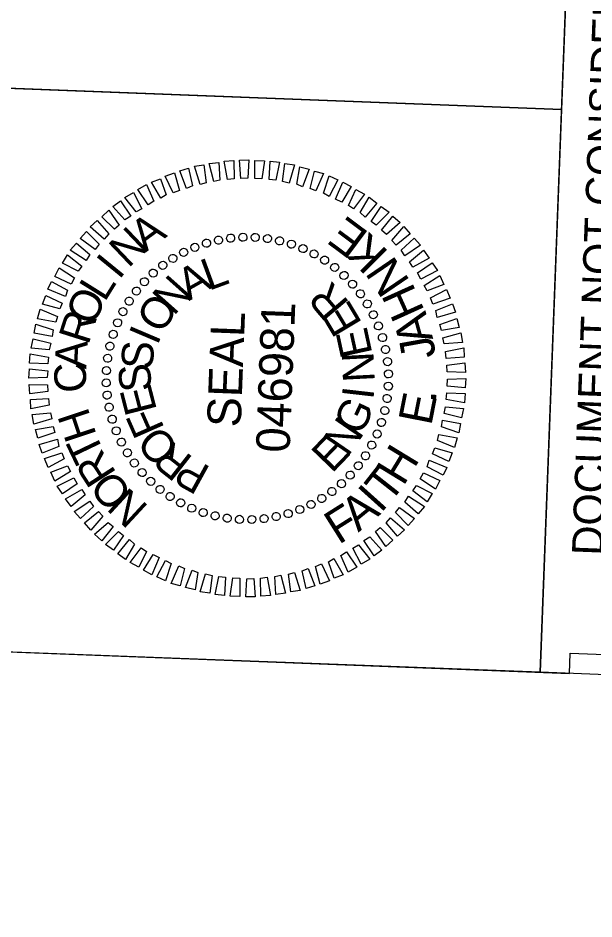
# Model space of a CAD drawing. Extents: x 2097521 to 2097987, y 686521 to 687299.
# Drawn here: x 2097571.8 to 2097612.8, y 687104.4 to 687168.4 of the extents above; entities that cross this region are included whole.
import ezdxf

# ---------------------------------------------------------------- set-up
doc = ezdxf.new("R2010")
doc.units = 0
for name, color, linetype in [('Sheet Layout Plan Border', 7, 'Continuous'), ('Sheet PE Seal Cell', 7, 'Continuous'), ('Sheet Profile CELL', 7, 'Continuous'), ('Sheet Sticker Exception Certification CELL', 7, 'Continuous')]:
    doc.layers.add(name, color=color, linetype=linetype)

msp = doc.modelspace()

# ---------------------------------------------------------------- linework, layer by layer
at = {"layer": 'Sheet Layout Plan Border'}
msp.add_lwpolyline([(2097534.777, 686624.292), (2097553.941, 687123.989), (2097611.015, 687121.8), (2097611.07, 687123.229), (2097798.297, 687116.048), (2097794.505, 687017.173), (2097779.163, 686617.133)], close=True, dxfattribs=at)
at = {"layer": 'Sheet PE Seal Cell'}
for p, q in [((2097586.055, 687152.587), (2097586.055, 687152.587)), ((2097586.941, 687152.714), (2097586.941, 687152.714)), ((2097587.805, 687152.801), (2097587.805, 687152.801)), ((2097588.685, 687152.787), (2097588.685, 687152.787)), ((2097589.562, 687152.693), (2097589.562, 687152.693)), ((2097590.416, 687152.52), (2097590.416, 687152.52)), ((2097584.395, 687152.091), (2097584.395, 687152.091)), ((2097585.207, 687152.38), (2097585.207, 687152.38)), ((2097591.248, 687152.308), (2097591.248, 687152.308)), ((2097592.077, 687151.996), (2097592.077, 687151.996)), ((2097582.823, 687151.29), (2097582.823, 687151.29)), ((2097583.6, 687151.721), (2097583.6, 687151.721)), ((2097592.863, 687151.606), (2097592.863, 687151.606)), ((2097593.627, 687151.176), (2097593.627, 687151.176)), ((2097582.104, 687150.818), (2097582.104, 687150.818)), ((2097594.327, 687150.649), (2097594.327, 687150.649)), ((2097581.422, 687150.243), (2097581.422, 687150.243)), ((2097595.006, 687150.083), (2097595.006, 687150.083)), ((2097580.799, 687149.647), (2097580.799, 687149.647)), ((2097595.602, 687149.459), (2097595.602, 687149.459)), ((2097580.232, 687148.968), (2097580.232, 687148.968)), ((2097596.177, 687148.777), (2097596.177, 687148.777)), ((2097579.705, 687148.268), (2097579.705, 687148.268)), ((2097596.649, 687148.058), (2097596.649, 687148.058)), ((2097579.275, 687147.504), (2097579.275, 687147.504)), ((2097597.08, 687147.281), (2097597.08, 687147.281)), ((2097578.885, 687146.718), (2097578.885, 687146.718)), ((2097597.45, 687146.486), (2097597.45, 687146.486)), ((2097578.573, 687145.889), (2097578.573, 687145.889)), ((2097597.739, 687145.675), (2097597.739, 687145.675)), ((2097578.361, 687145.057), (2097578.361, 687145.057)), ((2097597.947, 687144.826), (2097597.947, 687144.826)), ((2097578.188, 687144.203), (2097578.188, 687144.203)), ((2097598.073, 687143.941), (2097598.073, 687143.941)), ((2097578.094, 687143.326), (2097578.094, 687143.326)), ((2097598.16, 687143.077), (2097598.16, 687143.077)), ((2097578.081, 687142.446), (2097578.081, 687142.446)), ((2097588.12, 687142.761), (2097588.12, 687142.761)), ((2097598.146, 687142.196), (2097598.146, 687142.196)), ((2097578.168, 687141.582), (2097578.168, 687141.582)), ((2097598.052, 687141.319), (2097598.052, 687141.319)), ((2097578.294, 687140.696), (2097578.294, 687140.696)), ((2097597.879, 687140.465), (2097597.879, 687140.465)), ((2097578.501, 687139.848), (2097578.501, 687139.848)), ((2097597.667, 687139.633), (2097597.667, 687139.633)), ((2097578.791, 687139.036), (2097578.791, 687139.036)), ((2097597.355, 687138.804), (2097597.355, 687138.804)), ((2097579.16, 687138.241), (2097579.16, 687138.241)), ((2097596.965, 687138.019), (2097596.965, 687138.019)), ((2097579.591, 687137.464), (2097579.591, 687137.464)), ((2097596.535, 687137.255), (2097596.535, 687137.255)), ((2097580.064, 687136.745), (2097580.064, 687136.745)), ((2097596.008, 687136.554), (2097596.008, 687136.554)), ((2097580.638, 687136.063), (2097580.638, 687136.063)), ((2097595.442, 687135.875), (2097595.442, 687135.875)), ((2097581.235, 687135.44), (2097581.235, 687135.44)), ((2097594.818, 687135.279), (2097594.818, 687135.279)), ((2097581.913, 687134.873), (2097581.913, 687134.873)), ((2097594.136, 687134.705), (2097594.136, 687134.705)), ((2097582.614, 687134.346), (2097582.614, 687134.346)), ((2097583.378, 687133.916), (2097583.378, 687133.916)), ((2097593.417, 687134.232), (2097593.417, 687134.232)), ((2097584.163, 687133.526), (2097584.163, 687133.526)), ((2097584.992, 687133.214), (2097584.992, 687133.214)), ((2097591.845, 687133.432), (2097591.845, 687133.432)), ((2097592.64, 687133.801), (2097592.64, 687133.801)), ((2097585.824, 687133.002), (2097585.824, 687133.002)), ((2097586.678, 687132.829), (2097586.678, 687132.829)), ((2097587.556, 687132.735), (2097587.556, 687132.735)), ((2097588.436, 687132.722), (2097588.436, 687132.722)), ((2097589.3, 687132.809), (2097589.3, 687132.809)), ((2097590.185, 687132.935), (2097590.185, 687132.935)), ((2097591.034, 687133.142), (2097591.034, 687133.142))]:
    msp.add_line(p, q, dxfattribs=at)
for points in [[(2097586.7, 687156.886), (2097586.47, 687158.196), (2097587.152, 687158.23), (2097587.183, 687156.947)], [(2097587.664, 687156.969), (2097587.554, 687158.274), (2097588.235, 687158.288), (2097588.146, 687156.991)], [(2097588.664, 687156.951), (2097588.654, 687158.252), (2097589.334, 687158.226), (2097589.144, 687156.932)], [(2097589.663, 687156.892), (2097589.753, 687158.19), (2097590.411, 687158.125), (2097590.141, 687156.834)], [(2097583.794, 687156.257), (2097583.321, 687157.496), (2097583.949, 687157.692), (2097584.222, 687156.441)], [(2097584.766, 687156.54), (2097584.355, 687157.836), (2097585.019, 687157.931), (2097585.191, 687156.664)], [(2097585.734, 687156.743), (2097585.403, 687158.016), (2097586.087, 687158.11), (2097586.159, 687156.847)], [(2097590.618, 687156.756), (2097590.787, 687158.03), (2097591.464, 687157.924), (2097591.094, 687156.637)], [(2097591.631, 687156.557), (2097591.839, 687157.79), (2097592.513, 687157.624), (2097592.045, 687156.381)], [(2097581.966, 687155.566), (2097581.31, 687156.712), (2097581.939, 687156.948), (2097582.355, 687155.792)], [(2097582.841, 687155.933), (2097582.287, 687157.135), (2097582.936, 687157.371), (2097583.288, 687156.116)], [(2097592.581, 687156.26), (2097592.888, 687157.489), (2097593.542, 687157.324), (2097592.994, 687156.084)], [(2097593.529, 687155.924), (2097593.936, 687157.149), (2097594.545, 687156.865), (2097593.94, 687155.688)], [(2097581.067, 687155.08), (2097580.348, 687156.169), (2097580.962, 687156.526), (2097581.478, 687155.345)], [(2097594.393, 687155.49), (2097594.9, 687156.712), (2097595.508, 687156.388), (2097594.825, 687155.273)], [(2097580.228, 687154.592), (2097579.426, 687155.604), (2097580.02, 687155.961), (2097580.617, 687154.818)], [(2097595.297, 687155.055), (2097595.84, 687156.175), (2097596.448, 687155.852), (2097595.667, 687154.801)], [(2097596.138, 687154.543), (2097596.78, 687155.639), (2097597.324, 687155.218), (2097596.485, 687154.209)], [(2097579.425, 687154.023), (2097578.561, 687154.976), (2097579.117, 687155.375), (2097579.836, 687154.287)], [(2097596.914, 687153.912), (2097597.635, 687154.965), (2097598.2, 687154.563), (2097597.284, 687153.638)], [(2097578.679, 687153.351), (2097577.773, 687154.246), (2097578.271, 687154.707), (2097579.01, 687153.638)], [(2097577.952, 687152.658), (2097576.944, 687153.517), (2097577.442, 687153.979), (2097578.266, 687153.026)], [(2097597.65, 687153.284), (2097598.47, 687154.293), (2097598.972, 687153.833), (2097597.999, 687152.99)], [(2097577.303, 687151.922), (2097576.232, 687152.704), (2097576.692, 687153.207), (2097577.598, 687152.291)], [(2097598.383, 687152.555), (2097599.242, 687153.543), (2097599.682, 687153.026), (2097598.691, 687152.223)], [(2097599.057, 687151.869), (2097599.97, 687152.714), (2097600.432, 687152.216), (2097599.322, 687151.478)], [(2097576.672, 687151.126), (2097575.54, 687151.87), (2097575.98, 687152.373), (2097576.929, 687151.556)], [(2097599.646, 687151.045), (2097600.638, 687151.868), (2097601.037, 687151.312), (2097599.891, 687150.656)], [(2097576.103, 687150.367), (2097574.984, 687150.951), (2097575.347, 687151.537), (2097576.357, 687150.738)], [(2097575.608, 687149.466), (2097574.448, 687150.01), (2097574.751, 687150.619), (2097575.845, 687149.897)], [(2097600.217, 687150.263), (2097601.264, 687150.963), (2097601.624, 687150.429), (2097600.44, 687149.814)], [(2097600.682, 687149.365), (2097601.79, 687150.063), (2097602.086, 687149.431), (2097600.908, 687148.976)], [(2097575.194, 687148.581), (2097573.952, 687149.089), (2097574.214, 687149.639), (2097575.351, 687149.035)], [(2097574.799, 687147.695), (2097573.572, 687148.043), (2097573.795, 687148.654), (2097574.955, 687148.11)], [(2097601.129, 687148.487), (2097602.273, 687149.083), (2097602.529, 687148.453), (2097601.292, 687148.04)], [(2097601.515, 687147.591), (2097602.694, 687148.066), (2097602.911, 687147.458), (2097601.616, 687147.087)], [(2097574.503, 687146.746), (2097573.211, 687146.996), (2097573.397, 687147.669), (2097574.619, 687147.162)], [(2097601.797, 687146.6), (2097603.014, 687147.013), (2097603.17, 687146.387), (2097601.921, 687146.175)], [(2097574.244, 687145.735), (2097572.972, 687145.964), (2097573.097, 687146.62), (2097574.322, 687146.212)], [(2097602.02, 687145.631), (2097603.296, 687146.002), (2097603.409, 687145.317), (2097602.104, 687145.207)], [(2097574.047, 687144.782), (2097572.751, 687144.912), (2097572.896, 687145.567), (2097574.146, 687145.259)], [(2097602.203, 687144.663), (2097603.495, 687144.934), (2097603.529, 687144.272), (2097602.245, 687144.181)], [(2097573.949, 687143.785), (2097572.65, 687143.835), (2097572.695, 687144.494), (2097573.987, 687144.264)], [(2097573.892, 687142.826), (2097572.589, 687142.776), (2097572.635, 687143.435), (2097573.931, 687143.305)], [(2097602.287, 687143.699), (2097603.574, 687143.87), (2097603.628, 687143.187), (2097602.328, 687143.217)], [(2097573.954, 687141.823), (2097572.666, 687141.653), (2097572.612, 687142.335), (2097573.912, 687142.305)], [(2097602.348, 687142.696), (2097603.651, 687142.746), (2097603.606, 687142.087), (2097602.31, 687142.217)], [(2097602.291, 687141.737), (2097603.59, 687141.687), (2097603.545, 687141.029), (2097602.253, 687141.258)], [(2097574.037, 687140.859), (2097572.746, 687140.589), (2097572.711, 687141.251), (2097573.995, 687141.341)], [(2097574.22, 687139.892), (2097572.945, 687139.52), (2097572.831, 687140.205), (2097574.136, 687140.315)], [(2097602.193, 687140.74), (2097603.489, 687140.611), (2097603.344, 687139.956), (2097602.095, 687140.264)], [(2097601.996, 687139.787), (2097603.269, 687139.558), (2097603.143, 687138.903), (2097601.918, 687139.31)], [(2097574.443, 687138.922), (2097573.226, 687138.509), (2097573.07, 687139.135), (2097574.319, 687139.348)], [(2097574.725, 687137.931), (2097573.546, 687137.456), (2097573.329, 687138.065), (2097574.624, 687138.435)], [(2097601.737, 687138.776), (2097603.029, 687138.527), (2097602.843, 687137.853), (2097601.621, 687138.36)], [(2097601.441, 687137.827), (2097602.668, 687137.48), (2097602.445, 687136.868), (2097601.285, 687137.413)], [(2097575.111, 687137.035), (2097573.967, 687136.439), (2097573.711, 687137.069), (2097574.948, 687137.482)], [(2097575.558, 687136.158), (2097574.45, 687135.46), (2097574.154, 687136.091), (2097575.333, 687136.547)], [(2097601.047, 687136.941), (2097602.288, 687136.434), (2097602.027, 687135.883), (2097600.889, 687136.487)], [(2097600.632, 687136.057), (2097601.792, 687135.512), (2097601.489, 687134.903), (2097600.396, 687135.625)], [(2097576.024, 687135.259), (2097574.976, 687134.559), (2097574.616, 687135.093), (2097575.801, 687135.708)], [(2097600.138, 687135.155), (2097601.256, 687134.572), (2097600.893, 687133.985), (2097599.883, 687134.784)], [(2097576.594, 687134.477), (2097575.602, 687133.654), (2097575.203, 687134.21), (2097576.349, 687134.866)], [(2097577.183, 687133.654), (2097576.27, 687132.808), (2097575.809, 687133.306), (2097576.918, 687134.044)], [(2097599.568, 687134.396), (2097600.7, 687133.652), (2097600.261, 687133.149), (2097599.311, 687133.966)], [(2097577.857, 687132.967), (2097576.999, 687131.979), (2097576.558, 687132.497), (2097577.55, 687133.299)], [(2097598.937, 687133.6), (2097600.008, 687132.818), (2097599.548, 687132.315), (2097598.643, 687133.231)], [(2097598.288, 687132.864), (2097599.296, 687132.005), (2097598.798, 687131.544), (2097597.974, 687132.496)], [(2097578.59, 687132.239), (2097577.771, 687131.229), (2097577.268, 687131.689), (2097578.241, 687132.532)], [(2097597.561, 687132.172), (2097598.468, 687131.276), (2097597.97, 687130.815), (2097597.23, 687131.884)], [(2097579.326, 687131.61), (2097578.605, 687130.557), (2097578.04, 687130.959), (2097578.957, 687131.884)], [(2097580.103, 687130.98), (2097579.46, 687129.884), (2097578.916, 687130.305), (2097579.755, 687131.313)], [(2097596.815, 687131.5), (2097597.679, 687130.546), (2097597.123, 687130.147), (2097596.405, 687131.235)], [(2097580.944, 687130.467), (2097580.4, 687129.347), (2097579.792, 687129.671), (2097580.573, 687130.721)], [(2097596.013, 687130.93), (2097596.814, 687129.918), (2097596.22, 687129.561), (2097595.624, 687130.705)], [(2097581.848, 687130.032), (2097581.341, 687128.811), (2097580.733, 687129.134), (2097581.416, 687130.249)], [(2097595.173, 687130.442), (2097595.892, 687129.353), (2097595.278, 687128.997), (2097594.763, 687130.177)], [(2097582.712, 687129.599), (2097582.305, 687128.373), (2097581.695, 687128.657), (2097582.301, 687129.835)], [(2097583.66, 687129.262), (2097583.352, 687128.033), (2097582.698, 687128.198), (2097583.246, 687129.438)], [(2097593.399, 687129.589), (2097593.954, 687128.387), (2097593.304, 687128.152), (2097592.952, 687129.406)], [(2097594.274, 687129.956), (2097594.931, 687128.81), (2097594.301, 687128.574), (2097593.885, 687129.731)], [(2097584.609, 687128.966), (2097584.401, 687127.733), (2097583.727, 687127.899), (2097584.195, 687129.142)], [(2097585.622, 687128.767), (2097585.453, 687127.492), (2097584.777, 687127.598), (2097585.146, 687128.885)], [(2097590.506, 687128.779), (2097590.838, 687127.506), (2097590.153, 687127.412), (2097590.082, 687128.676)], [(2097591.475, 687128.982), (2097591.885, 687127.686), (2097591.221, 687127.591), (2097591.05, 687128.859)], [(2097592.446, 687129.265), (2097592.919, 687128.026), (2097592.291, 687127.83), (2097592.019, 687129.082)], [(2097586.577, 687128.63), (2097586.488, 687127.332), (2097585.83, 687127.398), (2097586.099, 687128.688)], [(2097587.576, 687128.572), (2097587.586, 687127.27), (2097586.907, 687127.296), (2097587.096, 687128.59)], [(2097588.576, 687128.553), (2097588.686, 687127.248), (2097588.005, 687127.234), (2097588.095, 687128.532)], [(2097589.54, 687128.636), (2097589.77, 687127.327), (2097589.088, 687127.293), (2097589.057, 687128.575)]]:
    msp.add_lwpolyline(points, close=True, dxfattribs=at)
for centre, major_axis in [((2097586.932, 687152.722), (-0.034, 0.286)), ((2097587.804, 687152.788), (-0.009, 0.288)), ((2097588.68, 687152.778), (0.016, 0.288)), ((2097584.394, 687152.075), (-0.107, 0.267)), ((2097585.22, 687152.365), (-0.083, 0.276)), ((2097586.068, 687152.581), (-0.059, 0.282)), ((2097589.55, 687152.691), (0.041, 0.285)), ((2097590.41, 687152.528), (0.066, 0.28)), ((2097591.253, 687152.291), (0.09, 0.274)), ((2097583.596, 687151.715), (-0.13, 0.257)), ((2097592.072, 687151.982), (0.113, 0.265)), ((2097592.86, 687151.603), (0.136, 0.254)), ((2097582.11, 687150.794), (-0.173, 0.231)), ((2097582.833, 687151.287), (-0.152, 0.245)), ((2097593.613, 687151.156), (0.158, 0.241)), ((2097581.433, 687150.239), (-0.192, 0.215)), ((2097594.324, 687150.645), (0.178, 0.226)), ((2097580.807, 687149.628), (-0.21, 0.197)), ((2097594.987, 687150.075), (0.197, 0.21)), ((2097580.236, 687148.964), (-0.226, 0.178)), ((2097595.598, 687149.448), (0.215, 0.192)), ((2097579.725, 687148.254), (-0.241, 0.158)), ((2097596.153, 687148.771), (0.231, 0.173)), ((2097596.646, 687148.048), (0.245, 0.152)), ((2097579.279, 687147.501), (-0.254, 0.136)), ((2097597.074, 687147.285), (0.257, 0.13)), ((2097578.899, 687146.713), (-0.265, 0.113)), ((2097597.434, 687146.487), (0.267, 0.107)), ((2097578.59, 687145.894), (-0.274, 0.09)), ((2097597.724, 687145.661), (0.276, 0.083)), ((2097578.353, 687145.051), (-0.28, 0.066)), ((2097597.94, 687144.813), (0.282, 0.059)), ((2097578.191, 687144.191), (-0.285, 0.041)), ((2097598.082, 687143.95), (0.286, 0.034)), ((2097578.104, 687143.32), (-0.288, 0.016)), ((2097598.147, 687143.077), (0.288, 0.009)), ((2097578.093, 687142.445), (-0.288, -0.009)), ((2097598.137, 687142.202), (0.288, -0.016)), ((2097578.159, 687141.573), (-0.286, -0.034)), ((2097598.05, 687141.331), (0.285, -0.041)), ((2097578.3, 687140.709), (-0.282, -0.059)), ((2097597.887, 687140.471), (0.28, -0.066)), ((2097578.517, 687139.861), (-0.276, -0.083)), ((2097597.65, 687139.628), (0.274, -0.09)), ((2097578.806, 687139.035), (-0.267, -0.107)), ((2097597.341, 687138.81), (0.265, -0.113)), ((2097579.166, 687138.237), (-0.257, -0.13)), ((2097596.962, 687138.021), (0.254, -0.136)), ((2097579.594, 687137.474), (-0.245, -0.152)), ((2097580.088, 687136.751), (-0.231, -0.173)), ((2097596.515, 687137.269), (0.241, -0.158)), ((2097580.642, 687136.074), (-0.215, -0.192)), ((2097596.004, 687136.558), (0.226, -0.178)), ((2097581.253, 687135.448), (-0.197, -0.21)), ((2097595.434, 687135.894), (0.21, -0.197)), ((2097581.917, 687134.877), (-0.178, -0.226)), ((2097594.807, 687135.283), (0.192, -0.215)), ((2097582.628, 687134.366), (-0.158, -0.241)), ((2097593.407, 687134.235), (0.152, -0.245)), ((2097594.13, 687134.729), (0.173, -0.231)), ((2097583.38, 687133.92), (-0.136, -0.254)), ((2097584.169, 687133.54), (-0.113, -0.265)), ((2097592.644, 687133.807), (0.13, -0.257)), ((2097584.987, 687133.231), (-0.09, -0.274)), ((2097585.83, 687132.994), (-0.066, -0.28)), ((2097590.172, 687132.941), (0.059, -0.282)), ((2097591.02, 687133.157), (0.083, -0.276)), ((2097591.846, 687133.447), (0.107, -0.267)), ((2097586.69, 687132.832), (-0.041, -0.285)), ((2097587.561, 687132.745), (-0.016, -0.288)), ((2097588.436, 687132.734), (0.009, -0.288)), ((2097589.309, 687132.8), (0.034, -0.286))]:
    msp.add_ellipse(centre, major_axis=major_axis, ratio=0.999708, dxfattribs=at)
at = {"layer": 'Sheet Profile CELL'}
msp.add_line((2097565.487, 687163.596), (2097610.434, 687161.872), dxfattribs=at)
for points in [[(2097565.487, 687163.596), (2097567.02, 687203.566), (2097611.987, 687201.842), (2097610.454, 687161.871)], [(2097563.954, 687123.605), (2097565.487, 687163.596), (2097610.454, 687161.871), (2097608.921, 687121.881)]]:
    msp.add_lwpolyline(points, close=True, dxfattribs=at)
at = {"layer": 'Sheet Sticker Exception Certification CELL'}
for p, q in [((2097608.921, 687121.881), (2097611.987, 687201.837)), ((2097618.314, 687121.52), (2097608.921, 687121.881))]:
    msp.add_line(p, q, dxfattribs=at)

# ---------------------------------------------------------------- texts
at = {"layer": 'Sheet PE Seal Cell'}
for s, height, rotation, p in [('A', 2.256, 36.42085, (2097580.877, 687151.685)), ('E', 2.399, 143.29672, (2097596.839, 687153.075)), ('N', 2.256, 43.62261, (2097579.652, 687150.551)), ('K', 2.399, 135.0128, (2097598.234, 687151.712)), ('I', 2.255, 50.82384, (2097579, 687149.716)), ('L', 2.256, 20.20455, (2097585.376, 687148.971)), ('N', 2.399, 124.28697, (2097599.723, 687149.673)), ('A', 2.256, 29.56397, (2097583.967, 687148.244)), ('N', 2.255, 48.28031, (2097582.884, 687147.145)), ('L', 2.255, 58.02457, (2097577.979, 687148.134)), ('R', 2.256, 130.28511, (2097595.431, 687148.125)), ('H', 2.399, 114.30299, (2097600.745, 687147.557)), ('O', 2.255, 65.22486, (2097577.172, 687146.403)), ('O', 2.255, 57.63718, (2097582.034, 687145.837)), ('046981', 2.3993, 87.8037, (2097591.122, 687137.454)), ('E', 2.255, 120.92779, (2097596.316, 687146.67)), ('R', 2.255, 72.4248, (2097576.821, 687145.076)), ('SEAL', 2.3993, 87.8037, (2097587.646, 687139.257)), ('A', 2.399, 105.46268, (2097601.333, 687145.56)), ('I', 2.255, 66.9933, (2097581.723, 687145.048)), ('E', 2.255, 102.21546, (2097597.014, 687144.522)), ('A', 2.255, 86.82402, (2097576.676, 687143.4)), ('J', 2.399, 100.20486, (2097601.533, 687144.337)), ('S', 2.255, 85.7041, (2097581.377, 687143.34)), ('N', 2.255, 92.86009, (2097597.178, 687142.534)), ('C', 2.255, 94.02357, (2097576.736, 687141.817)), ('S', 2.255, 95.05931, (2097581.342, 687141.9)), ('E', 2.255, 104.41477, (2097581.709, 687140.505)), ('I', 2.255, 83.5049, (2097597.067, 687141.197)), ('E', 2.399, 78.86139, (2097601.187, 687139.347)), ('.', 2.399, 85.97073, (2097601.509, 687140.991)), ('G', 2.255, 64.79394, (2097596.207, 687138.608)), ('H', 2.255, 108.42318, (2097577.419, 687138.748)), ('F', 2.255, 113.77073, (2097582.26, 687139.203)), ('N', 2.255, 55.43766, (2097595.249, 687137.124)), ('O', 2.256, 132.48494, (2097583.388, 687137.839)), ('T', 2.255, 115.62347, (2097578.028, 687137.424)), ('R', 2.256, 141.84335, (2097584.341, 687137.102)), ('E', 2.255, 46.08059, (2097594.124, 687135.966)), ('R', 2.255, 122.82421, (2097578.855, 687136.031)), ('H', 2.399, 58.67705, (2097599.207, 687135.048)), ('P', 2.256, 151.20259, (2097585.595, 687136.413)), ('T', 2.399, 51.87681, (2097598.215, 687133.79)), ('O', 2.255, 130.02544, (2097580.042, 687134.605)), ('I', 2.399, 48.07486, (2097597.598, 687133.14)), ('N', 2.256, 137.2272, (2097581.166, 687133.641)), ('F', 2.399, 32.21794, (2097594.609, 687130.916)), ('A', 2.399, 39.23455, (2097596.007, 687131.798))]:
    msp.add_text(s, height=height, rotation=rotation, dxfattribs=at).set_placement(p)
at = {"layer": 'Sheet Sticker Exception Certification CELL'}
msp.add_text('DOCUMENT NOT CONSIDERED FINAL', height=2.2, rotation=87.8037, dxfattribs=at).set_placement((2097613.379, 687130.144))

doc.saveas('drawing.dxf')
